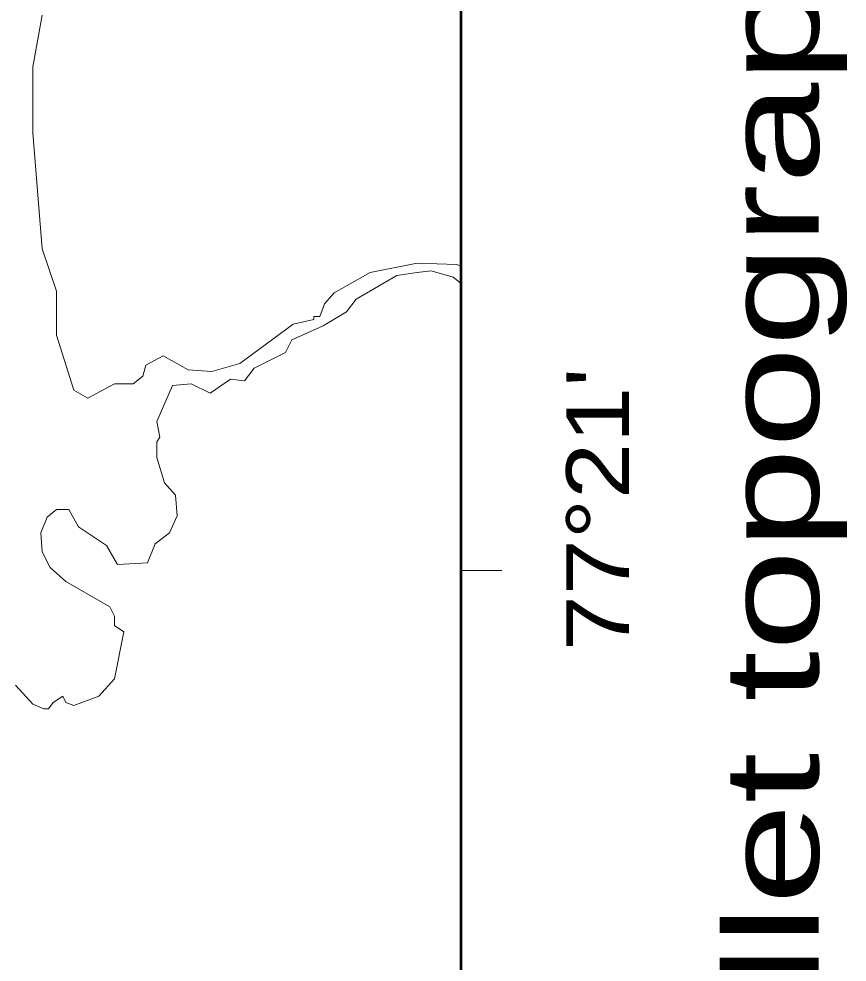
# Model space of a CAD drawing. Extents: x 240591 to 242335, y 5323482 to 5326937.
# Drawn here: x 241578.7 to 241631.5, y 5326602 to 5326662.2 of the extents above; entities that cross this region are included whole.
import ezdxf
from ezdxf.enums import TextEntityAlignment as Align

# ---------------------------------------------------------------- set-up
doc = ezdxf.new("R2010")
doc.units = 0
doc.header["$LTSCALE"] = 1.2
doc.layers.add('63', color=7, linetype='Continuous', lineweight=13)

msp = doc.modelspace()

# ---------------------------------------------------------------- linework, layer by layer
at = {"layer": '63'}
msp.add_line((241606.9, 5326627), (241609.5, 5326627), dxfattribs=at)
at = {"layer": '63', "lineweight": 53}
msp.add_lwpolyline([(241606.9, 5326533.9), (241606.9, 5326741.9), (241450.9, 5326741.9), (241450.9, 5326533.9)], close=True, dxfattribs=at)
at = {"layer": '63'}
for points in [[(241578.5, 5326619.7), (241579.6, 5326618.5), (241580.3, 5326618.2), (241580.6, 5326618.2), (241580.9, 5326618.6), (241581.5, 5326619), (241581.7, 5326618.6), (241582.2, 5326618.4), (241583.8, 5326619), (241584.8, 5326620.1), (241585.4, 5326623.1), (241584.8, 5326623.5), (241584.8, 5326624.1), (241584.5, 5326624.7), (241581.7, 5326626.3), (241580.7, 5326627.2), (241580.2, 5326628.2), (241580.1, 5326629.4), (241580.5, 5326630.4), (241581.1, 5326630.9), (241581.9, 5326630.9), (241582.5, 5326629.8), (241584.3, 5326628.6), (241585, 5326627.4), (241586.9, 5326627.5), (241587.4, 5326628.7), (241588.3, 5326629.4), (241588.8, 5326630.5), (241588.7, 5326631.8), (241588, 5326632.6), (241587.5, 5326634.2), (241587.5, 5326635.2), (241587.7, 5326635.5), (241587.5, 5326636.5), (241588.5, 5326638.8), (241589.7, 5326638.9), (241590.9, 5326638.3), (241592.2, 5326639.2), (241593.1, 5326639.1), (241593.7, 5326639.9), (241595.7, 5326640.9), (241596.1, 5326641.7), (241598.1, 5326642.6), (241599.6, 5326643.5), (241600.2, 5326644.3), (241602.8, 5326645.8), (241604.1, 5326646), (241605, 5326646.1), (241606.4, 5326645.7), (241606.9, 5326645.3), (241606.9, 5326646.4), (241606.6, 5326646.5), (241604.1, 5326646.6), (241601.1, 5326646), (241598.8, 5326644.7), (241598.2, 5326644), (241597.9, 5326643.2), (241597.5, 5326643.2), (241597.5, 5326643), (241596.2, 5326642.7), (241592.8, 5326640.2), (241591, 5326639.7), (241589.5, 5326639.8), (241587.9, 5326640.7), (241586.8, 5326640.1), (241586.6, 5326639.4), (241586, 5326638.9), (241584.8, 5326638.9), (241583.1, 5326638), (241582.2, 5326638.5), (241581.1, 5326642), (241581.1, 5326644.8), (241580.2, 5326647.5), (241579.6, 5326654.9), (241579.6, 5326659.1), (241580.2, 5326662.4)], [(241597.5, 5326643.2), (241597.5, 5326643), (241596.2, 5326642.7), (241592.8, 5326640.2), (241591, 5326639.7), (241589.5, 5326639.8), (241587.9, 5326640.7), (241586.8, 5326640.1), (241586.6, 5326639.4), (241586, 5326638.9), (241584.8, 5326638.9), (241583.1, 5326638), (241582.2, 5326638.5), (241581.1, 5326642), (241581.1, 5326644.8), (241580.2, 5326647.5), (241579.6, 5326654.9), (241579.6, 5326659.1), (241580.2, 5326662.4)], [(241597.5, 5326643.2), (241597.9, 5326643.2), (241598.2, 5326644), (241598.8, 5326644.7), (241601.1, 5326646), (241604.1, 5326646.6), (241606.6, 5326646.5), (241606.9, 5326646.4)], [(241598.1, 5326642.6), (241599.6, 5326643.5), (241600.2, 5326644.3), (241602.8, 5326645.8), (241604.1, 5326646), (241605, 5326646.1), (241606.4, 5326645.7), (241606.9, 5326645.3)], [(241582.2, 5326618.4), (241583.8, 5326619), (241584.8, 5326620.1), (241585.4, 5326623.1), (241584.8, 5326623.5), (241584.8, 5326624.1), (241584.5, 5326624.7), (241581.7, 5326626.3), (241580.7, 5326627.2), (241580.2, 5326628.2), (241580.1, 5326629.4), (241580.5, 5326630.4), (241581.1, 5326630.9), (241581.9, 5326630.9), (241582.5, 5326629.8), (241584.3, 5326628.6), (241585, 5326627.4), (241586.9, 5326627.5), (241587.4, 5326628.7), (241588.3, 5326629.4), (241588.8, 5326630.5), (241588.7, 5326631.8), (241588, 5326632.6), (241587.5, 5326634.2), (241587.5, 5326635.2), (241587.7, 5326635.5), (241587.5, 5326636.5), (241588.5, 5326638.8), (241589.7, 5326638.9), (241590.9, 5326638.3), (241592.2, 5326639.2), (241593.1, 5326639.1), (241593.7, 5326639.9), (241595.7, 5326640.9), (241596.1, 5326641.7), (241598.1, 5326642.6)], [(241582.2, 5326618.4), (241581.7, 5326618.6), (241581.5, 5326619), (241580.9, 5326618.6), (241580.6, 5326618.2), (241580.3, 5326618.2), (241579.6, 5326618.5), (241578.5, 5326619.7)]]:
    msp.add_lwpolyline(points, dxfattribs=at)

# ---------------------------------------------------------------- texts
for s, height, width, p in [('Feuillet topographique national : 32C03', 6, 1.45, (241629.7, 5326679.45)), ("77°21'", 4, 1.2, (241617.6, 5326630.9))]:
    msp.add_text(s, height=height, rotation=90, dxfattribs=dict(at, width=width)).set_placement(p, align=Align.CENTER)

doc.saveas('drawing.dxf')
